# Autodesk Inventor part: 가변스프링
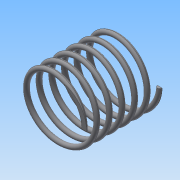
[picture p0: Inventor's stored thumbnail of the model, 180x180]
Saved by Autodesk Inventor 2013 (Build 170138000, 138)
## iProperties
Created: 2018-02
Part Number: 가변스프링
Material: 일반
Document SubType Name: Modeling
Designer: Administrator
Density: 1 g/cm^3
Mass: -0.0582704 g
Surface Area: 70.8526 cm^2
Volume: -0.0582704 cm^3
Author: Administrator
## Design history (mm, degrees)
sketch "스케치1"
  geometry: L1 (0, 0)-(20, 0); L2 (20, 0)-(20, 47.25); L3 (20, 47.25)-(0, 47.25); L4 (0, 47.25)-(0, 0); C1 r 1.5 at (20, 0)
  constraints: 8 end point, 2 parallel, 1 centre point, 1 horizontal, 1 perpendicular
  dimensions: "d0" = 3 diameter of C1; "d1" = 40 diameter of L2 L4; "d2" = 47.25 distance of L3.end L1.start (derived)
feature "코일1" sketch "스케치1" pitch "d3" = 10; turns "d5" = 6; dims "d4" = 47.25 (= d2), "d6" = 0, angle "d7" = 90 deg, angle "d8" = 90 deg, "d9" = 0, "d10" = 0
sketch "스케치2"
  geometry: L1 (-25, 47.25)-(25, 47.25); L2 (25, 47.25)-(25, 0); L3 (25, 0)-(-25, 0); L4 (-25, 0)-(-25, 47.25); 6 further points
  constraints: 8 end point, 2 horizontal alignment, 2 parallel, 2 point on line, 1 horizontal, 1 midpoint, 1 perpendicular, 1 vertical alignment
  dimensions: "d11" = 50 distance between parallel lines of L4 L2
extrude "돌출1" sketch "스케치2" stored distance "d13" = 0; taper "d14" = 0 deg
node "솔리드1"
